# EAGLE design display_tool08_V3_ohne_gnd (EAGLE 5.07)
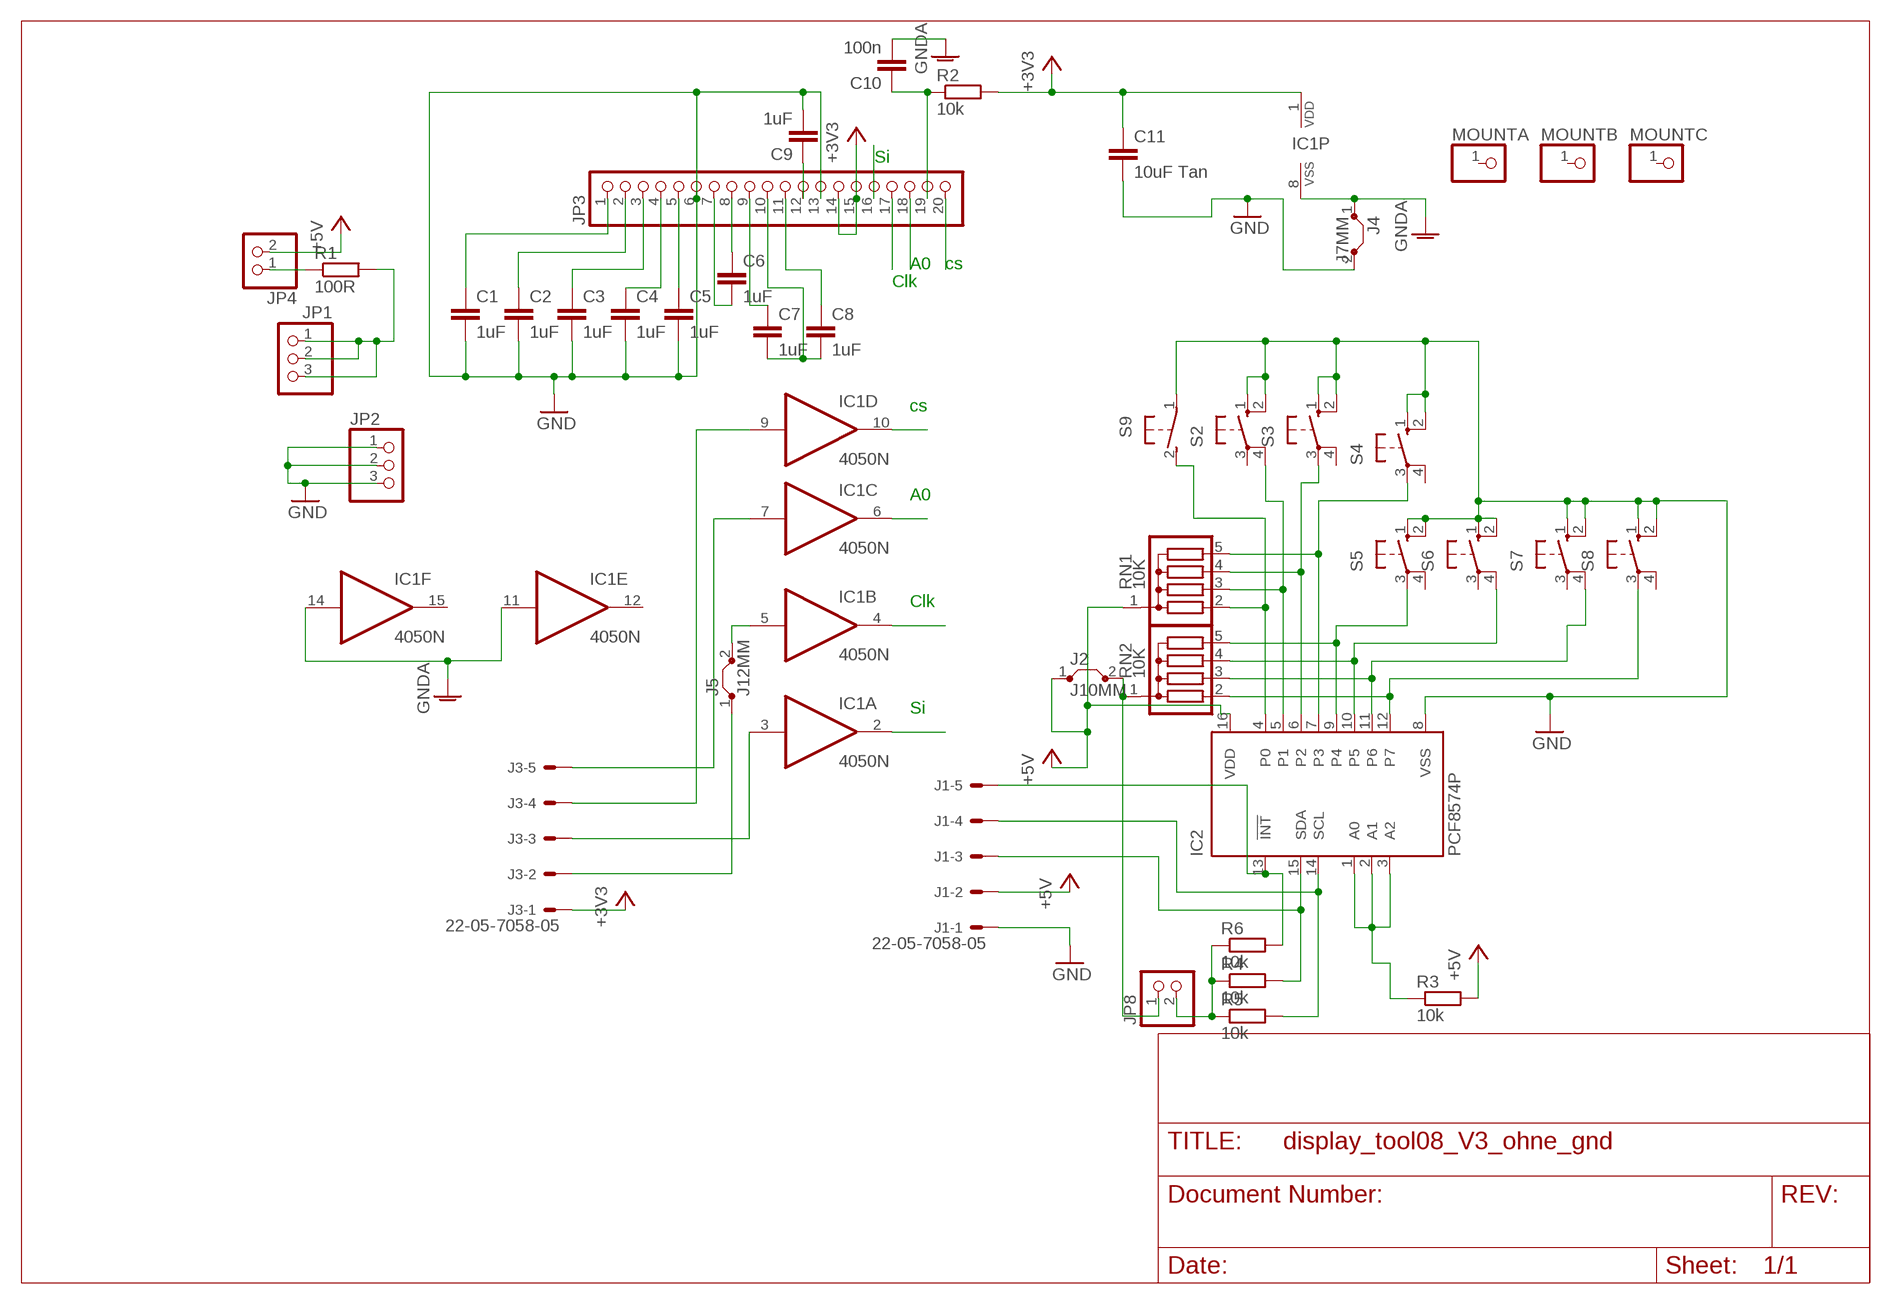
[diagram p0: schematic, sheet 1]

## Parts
C1  1uF  C-EU025-025X050  [C025-025X050]
C2  1uF  C-EU025-025X050  [C025-025X050]
C3  1uF  C-EU025-025X050  [C025-025X050]
C4  1uF  C-EU025-025X050  [C025-025X050]
C5  1uF  C-EU025-025X050  [C025-025X050]
C6  1uF  C-EU025-025X050  [C025-025X050]
C7  1uF  C-EU025-025X050  [C025-025X050]
C8  1uF  C-EU025-025X050  [C025-025X050]
C9  1uF  C-EU025-025X050  [C025-025X050]
C10  100n  C-EU025-025X050  [C025-025X050]
C11  10uF Tan  C-EU025-025X050  [C025-025X050]
IC1  4050N  [DIL16]
IC2  PCF8574P  [DIL16]
J1  22-05-7058-05  [7395-05]
J2  J10MM  [10]
J3  22-05-7058-05  [7395-05]
J4  J7MM  [07]
J5  J12MM  [12]
JP1  PINHD-1X3  [1X03]
JP2  PINHD-1X3  [1X03]
JP3  PINHD-1X20  [1X20]
JP4  PINHD-1X2  [1X02]
JP8  PINHD-1X2  [1X02]
MOUNTA  PINHD-1X1  [1X01]
MOUNTB  PINHD-1X1  [1X01]
MOUNTC  PINHD-1X1  [1X01]
R1  100R  R-EU_0309/12  [0309/12]
R2  10k  R-EU_0309/12  [0309/12]
R3  10k  R-EU_0207/7  [0207/7]
R4  10k  R-EU_0207/7  [0207/7]
R5  10k  R-EU_0207/7  [0207/7]
R6  10k  R-EU_0207/7  [0207/7]
RN1  10K  G04R  [SIL5]
RN2  10K  G04R  [SIL5]
S2  10-XX  [B3F-10XX]
S3  10-XX  [B3F-10XX]
S4  10-XX  [B3F-10XX]
S5  10-XX  [B3F-10XX]
S6  10-XX  [B3F-10XX]
S7  10-XX  [B3F-10XX]
S8  10-XX  [B3F-10XX]
S9  31-XX  [B3F-31XX]

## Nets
+3V3 [big]: C11.1 IC1.1(P:VDD) J3.1 JP3.14 JP3.15 R2.2
+5V: IC2.16(VDD) J1.2 J2.1 JP4.2 R3.2 RN1.1
A0 [big]: IC1.6(C:O) JP3.18
CLK: IC1.4(B:O) JP3.17
CS [signal]: IC1.10(D:O) JP3.20
GND: C1.2 C2.2 C3.2 C4.2 C5.2 C9.2 C11.2 IC2.8(VSS) J1.1 J4.2 JP2.1 JP2.2 JP2.3 JP3.6 JP3.13 S2.1(S) S2.2(S1) S3.1(S) S3.2(S1) S4.1(S) S4.2(S1) S5.1(S) S5.2(S1) S6.1(S) S6.2(S1) S7.1(S) S7.2(S1) S8.1(S) S8.2(S1) S9.1(P)
GNDA: C10.2 IC1.8(P:VSS) IC1.11(E:I) IC1.14(F:I) J4.1
N$1: JP4.1 R1.1
N$2: JP1.1 JP1.2 JP1.3 R1.2
N$3: IC2.7(P3) RN1.5 S4.3(P)
N$4: IC2.12(P7) RN2.2 S8.3(P)
N$5 [big]: C1.1 JP3.1
N$6 [big]: C2.1 JP3.2
N$7 [big]: C3.1 JP3.3
N$8 [big]: C4.1 JP3.4
N$9 [big]: C5.1 JP3.5
N$10: IC2.6(P2) RN1.4 S3.3(P)
N$11: IC2.11(P6) RN2.3 S7.4(P1)
N$12 [big]: C6.2 JP3.7
N$13 [big]: C6.1 JP3.8
N$14 [big]: C7.2 C8.2 JP3.10
N$15: IC2.5(P1) RN1.3 S2.4(P1)
N$16 [big]: C7.1 JP3.9
N$17 [big]: C8.1 JP3.11
N$18 [big]: C9.1 JP3.12
N$19 [big]: C10.1 JP3.19 R2.1
N$20: IC2.10(P5) RN2.4 S6.4(P1)
N$21: IC2.4(P0) RN1.2 S9.2(S)
N$22: IC2.9(P4) RN2.5 S5.3(P)
N$25 [signal]: IC1.3(A:I) J3.3
N$26 [big]: J3.2 J5.1
N$27 [signal]: IC1.7(C:I) J3.5
N$28: IC1.9(D:I) J3.4
N$29 [big]: IC1.5(B:I) J5.2
N$30: IC2.13(!INT) J1.5 R6.2
N$31: IC2.1(A0) IC2.2(A1) IC2.3(A2) R3.1
N$34: J2.2 JP8.1 RN2.1
N$35: JP8.2 R4.1 R5.1 R6.1
SCL: IC2.14(SCL) J1.4 R5.2
SDA: IC2.15(SDA) J1.3 R4.2
SI: IC1.2(A:O) JP3.16
Unconnected: IC1.12(E:O) IC1.15(F:O) MOUNTA.1 MOUNTB.1 MOUNTC.1 S2.3(P) S3.4(P1) S4.4(P1) S5.4(P1) S6.3(P) S7.3(P) S8.4(P1)

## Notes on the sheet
- Si
- A0 | cs
- Clk
- cs
- A0
- Clk
- Si

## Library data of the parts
C1-C11 = rcl:C-EU: CAPACITOR, European symbol
IC1 = 40xx:4050: Hex non-inverting BUFFER
IC2 = micro-philips:PCF8574: I2C-Bus Remote 8-bit I/O expander http://www.semiconductors.philips.com/acrobat_download/datasheets/PCF8574_4.pdf
J1 J3 = con-molex:22-?-05: CONNECTOR wire to board 2.54 mm (.1 inch) pitch header
J2 J4 J5 = jumper:J: Bridge
JP1 JP2 = pinhead:PINHD-1X3: PIN HEADER
JP3 = pinhead:PINHD-1X20: PIN HEADER
JP4 JP8 = pinhead:PINHD-1X2: PIN HEADER
MOUNTA MOUNTB MOUNTC = pinhead:PINHD-1X1: PIN HEADER
R1-R6 = rcl:R-EU_: RESISTOR, European symbol
RN1 RN2 = resistor-sil:G04R: SIL RESISTOR
S2-S8 = switch-omron:10-XX: OMRON SWITCH
S9 = switch-omron:31-XX: OMRON SWITCH

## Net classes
0 default: width 0.813 mm, drill 1.016 mm, clearance 0.762 mm
1 signal: width 0.813 mm, drill 1.016 mm, clearance 0.762 mm to class 0, clearance 0.762 mm
2 big: width 1.27 mm, clearance 0.762 mm to class 0, clearance 0.762 mm to class 1, clearance 0.762 mm

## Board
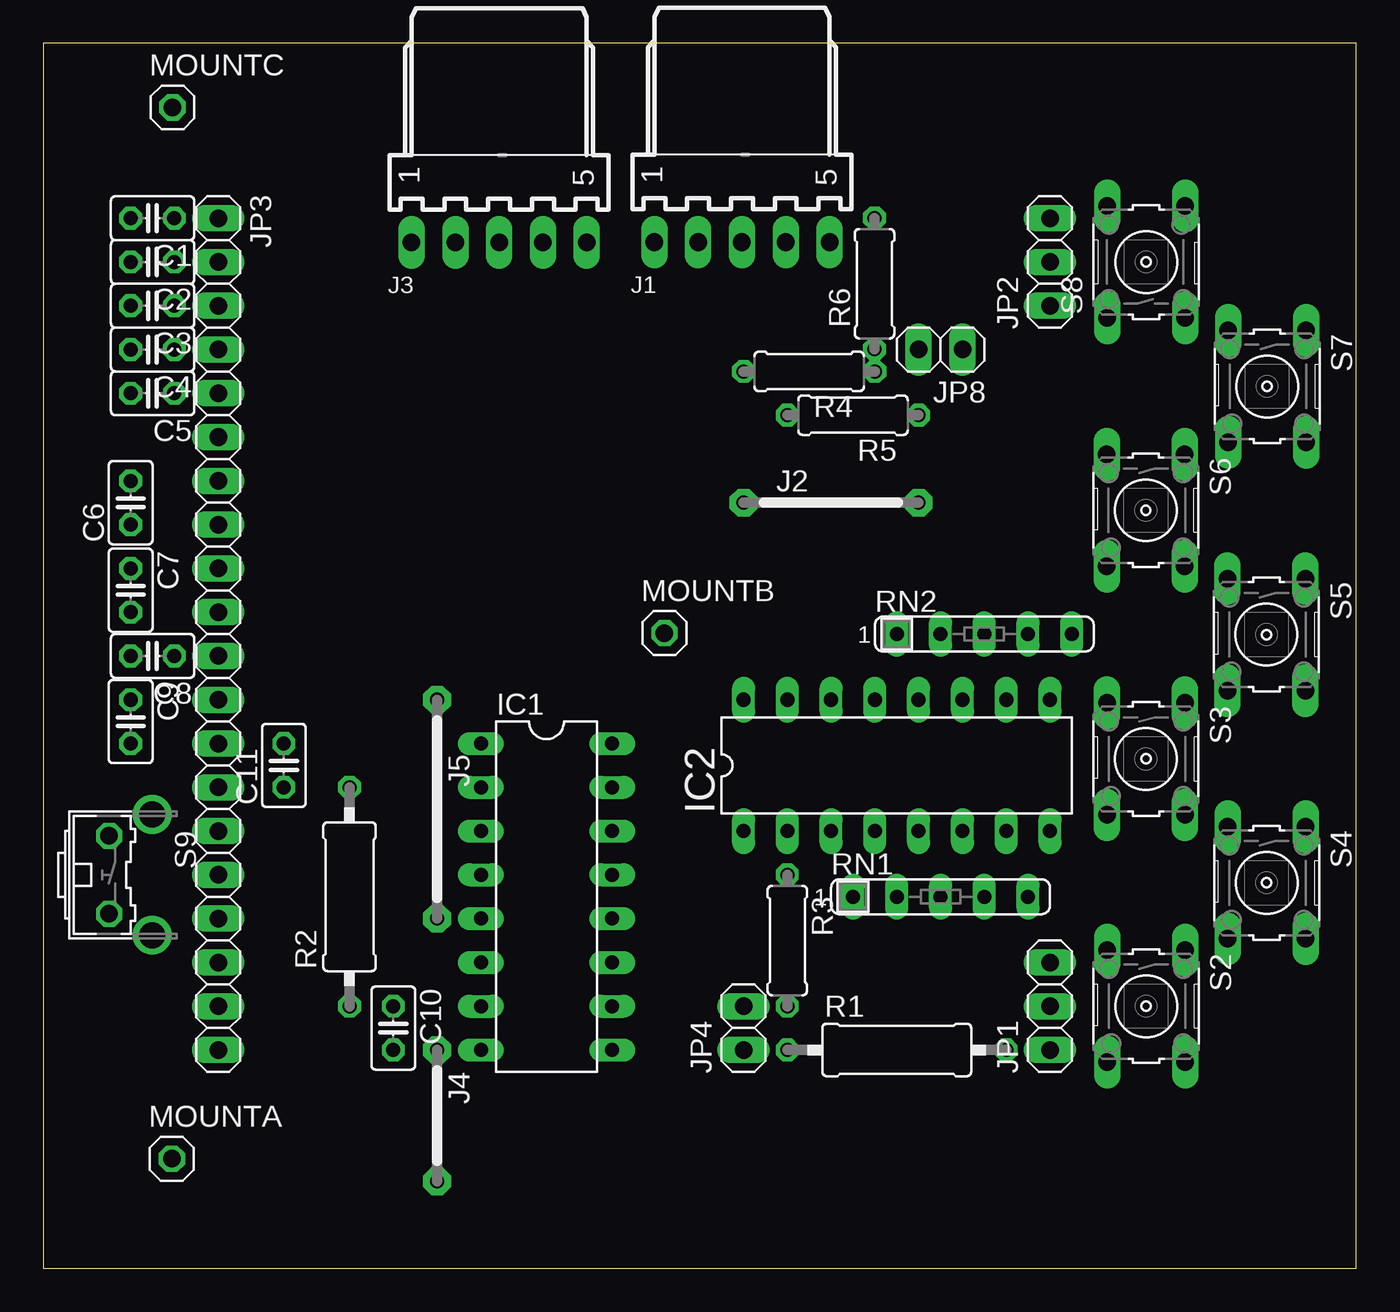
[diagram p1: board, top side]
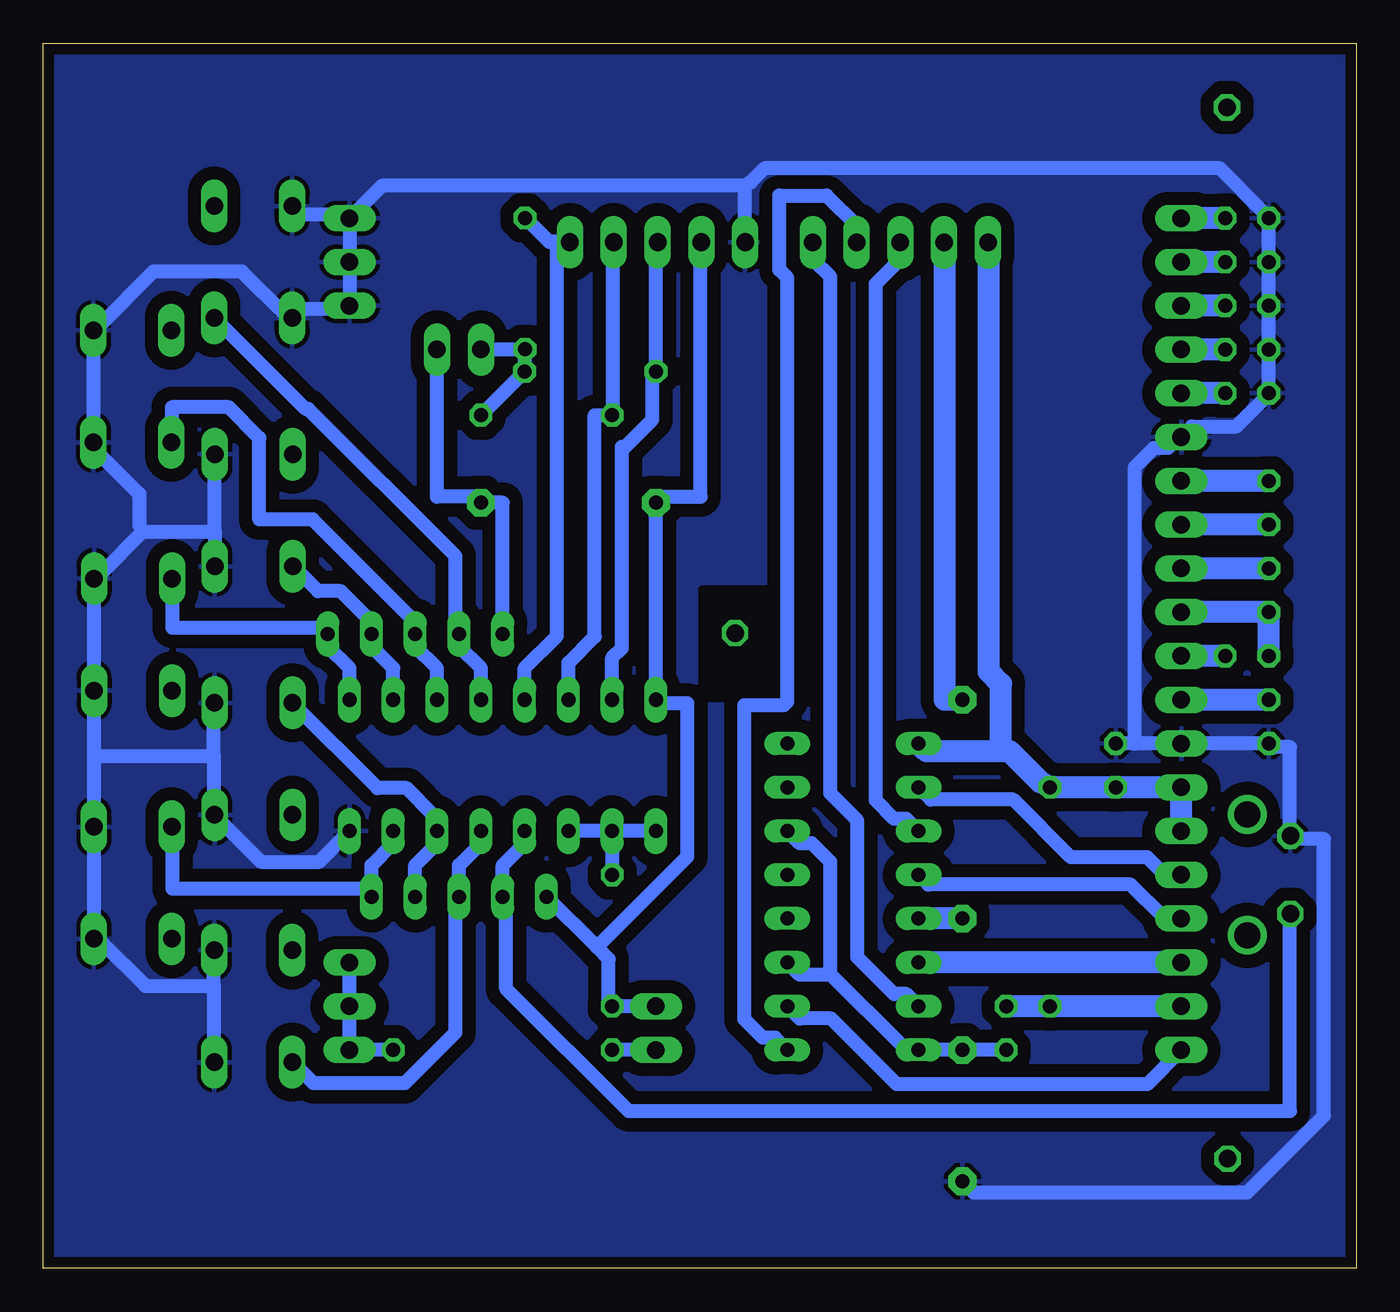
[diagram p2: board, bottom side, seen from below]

Size 76.2 x 71.12 mm. Coordinates in mm from the lower left corner, seen from the top.
Outline: 76.19,0.03 0,0.03 0,71.12 76.2,71.12 76.2,0
Copper layers (1*16): Top 0.035mm / dielectric 1.5mm / Bottom 0.035mm
Design rules "default *": minimum track width 10mil, minimum drill 24mil, track to track 8mil, track to pad 8mil, pad to pad 8mil, via to via 8mil, smd to smd 8mil, copper to edge 25mil, drill to drill 8mil, minimum pad ring 10mil, minimum via ring 8mil, stop-mask expansion 4mil, vias tented up to drill 0mil, thermal gap 10mil
bRestrict: area 33.4,33.1 to 37.9,39.4

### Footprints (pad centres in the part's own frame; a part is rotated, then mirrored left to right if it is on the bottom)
C025-025X050 = drill 0.813 octagon: 1 -1.27,0; 2 1.27,0
DIL16 = drill 0.813 long: 1 -8.89,-3.81; 2 -6.35,-3.81; 3 -3.81,-3.81; 4 -1.27,-3.81; 5 1.27,-3.81; 6 3.81,-3.81; 7 6.35,-3.81; 8 8.89,-3.81; 9 8.89,3.81; 10 6.35,3.81; 11 3.81,3.81; 12 1.27,3.81; 13 -1.27,3.81; 14 -3.81,3.81; 15 -6.35,3.81; 16 -8.89,3.81
7395-05 = drill 1.016 long: 1 5.08,0; 2 2.54,0; 3 0,0; 4 -2.54,0; 5 -5.08,0
10 = drill 0.813 pad 1.6 octagon: 1 -5.08,0; 2 5.08,0
07 = drill 0.813 pad 1.6 octagon: 1 -3.81,0; 2 3.81,0
12 = drill 0.813 pad 1.6 octagon: 1 -6.35,0; 2 6.35,0
1X03 = drill 1.016 long: 1 -2.54,0; 2 0,0; 3 2.54,0
1X20 = drill 1.016 long: 1 -24.13,0; 2 -21.59,0; 3 -19.05,0; 4 -16.51,0; 5 -13.97,0; 6 -11.43,0; 7 -8.89,0; 8 -6.35,0; 9 -3.81,0; 10 -1.27,0; 11 1.27,0; 12 3.81,0; 13 6.35,0; 14 8.89,0; 15 11.43,0; 16 13.97,0; 17 16.51,0; 18 19.05,0; 19 21.59,0; 20 24.13,0
1X02 = drill 1.016 long: 1 -1.27,0; 2 1.27,0
1X01 = drill 1.016 octagon: 1 0,0
0309/12 = drill 0.813 octagon: 1 -6.35,0; 2 6.35,0
0207/7 = drill 0.813 octagon: 1 -3.81,0; 2 3.81,0
SIL5 = drill 0.813 long: 1 -5.08,0; 2 -2.54,0; 3 0,0; 4 2.54,0; 5 5.08,0
B3F-10XX = drill 1.016 long: 1 -3.251,2.261; 2 3.251,2.261; 3 -3.251,-2.261; 4 3.251,-2.261
B3F-31XX = drill 1.016 octagon: 1 -2.261,-1.245; 2 2.261,-1.245 | drill 1.499 pad 2.159 round: 3 -3.505,1.245; 4 3.505,1.245

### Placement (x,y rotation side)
C1  6.35,60.96 180 top
C2  6.35,58.42 180 top
C3  6.35,55.88 180 top
C4  6.35,53.34 180 top
C5  6.35,50.8 180 top
C6  5.08,44.45 90 top
C7  5.08,39.37 270 top
C8  6.35,35.56 180 top
C9  5.08,31.75 270 top
C10  20.32,13.97 270 top
C11  13.97,29.21 90 top
IC1  29.21,21.59 270 top
IC2  49.53,29.21 0 top
J1  40.55,59.57 180 top
J2  45.72,44.45 0 top
J3  26.46,59.55 180 top
J4  22.86,8.89 270 top
J5  22.86,26.67 270 top
JP1  58.42,15.24 90 top
JP2  58.42,58.42 90 top
JP3  10.16,36.83 270 top
JP4  40.64,13.97 90 top
JP8  52.07,53.34 180 top
MOUNTA  7.47,6.39 0 top
MOUNTB  36.05,36.89 0 top
MOUNTC  7.51,67.39 0 top
R1  49.53,12.7 0 top
R2  17.78,21.59 90 top
R3  43.18,19.05 270 top
R4  44.45,52.07 180 top
R5  46.99,49.53 180 top
R6  48.24,57.16 90 top
RN1  52.07,21.59 0 top
RN2  54.61,36.83 0 top
S2  64,15.24 270 top
S3  63.99,29.59 270 top
S4  70.99,22.4 270 top
S5  70.98,36.8 270 top
S6  63.98,44.01 270 top
S7  71.02,51.2 270 top
S8  64,58.42 90 top
S9  5.08,22.86 270 top

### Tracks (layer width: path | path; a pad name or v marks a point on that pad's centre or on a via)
+3V3
  Bottom 1.27: IC1.1 24.94,30.02 20.62,30.02 | 20.62,30.02 20.12,30.02 18.34,28.25 R2.2 C11.1 JP3.14 JP3.15 | J3.1 21.34,59.54 21.34,34.65 20.62,33.93 20.62,30.02
+5V
  Bottom 0.813: JP4.2 R3.2 43.38,15.6 43.38,17.98 44.07,18.67 | 44.07,18.67 RN1.1 | J1.2 38.05,59.54 38.05,44.81 40.44,44.81 J2.1 IC2.16 40.28,32.82 38.81,32.82 38.81,23.93 44.07,18.67
A0
  Bottom 1.27: JP3.18 IC1.6
CLK
  Bottom 0.813: IC1.4 24.84,22.3 13.11,22.3 11.12,20.32 JP3.17
CS
  Bottom 0.813: IC1.10 32.31,14.53 30.48,14.53 26.67,10.72 12.14,10.72 JP3.20
GND
  Bottom 0.813: 12.85,30.48 C11.2 | 12.85,30.48 JP3.13 C9.2 4.72,30.28 3.86,30.28 3.86,25.15 S9.1 3.45,24.94 1.88,24.94 1.88,8.89 6.35,4.42 22.2,4.42 J4.2 | 12.85,30.48 12.85,46.53 11.73,47.65 10.92,47.65 10.52,48.06 JP3.6 9.55,48.87 6.96,48.87 5.33,50.49 C5.2 C4.2 C3.2 C2.2 C1.2 5.33,61.27 7.92,63.86 34.34,63.86 35.15,63.04 35.51,62.84 | 35.51,62.84 35.51,59.59 J1.1 | 35.51,62.84 56.54,62.84 JP2.3 | S8.2 61.72,61.67 61.21,61.16 58.78,61.16 JP2.3 | JP2.3 JP2.2 JP2.1 58.78,55.68 61.21,55.68 61.72,55.17 S8.1 62.13,55.32 64.67,57.86 69.8,57.86 72.95,54.71 S7.1 73.3,54.41 73.3,47.95 S7.2 73.2,47.55 70.61,44.96 70.61,43.13 70.41,42.77 | IC2.8 60.2,23.62 63.55,23.62 66.24,26.31 S3.2 66.29,26.72 66.29,29.77 | 66.29,29.77 66.29,32.82 S3.1 | 66.24,42.77 66.24,47.24 S6.1 | 66.24,42.77 66.24,40.79 S6.2 | 66.29,16.41 66.29,18.49 S2.1 | 66.29,16.41 66.29,11.99 S2.2 | 66.29,16.41 70.26,16.41 72.85,19 S4.2 73.25,25.6 S4.1 73.3,26.06 73.25,26.06 73.25,29.77 | 73.25,29.77 73.25,33.12 S5.2 73.25,33.58 73.25,40.03 S5.1 72.9,40.28 70.41,42.77 | 70.41,42.77 66.24,42.77 | 73.25,29.77 66.29,29.77
  pour Bottom (isolate 0.25): 0.25,0 76.15,0 76.15,71.07 0.15,71.07 0.15,-0.15
GNDA
  Bottom 0.813: C10.2 J4.1 IC1.8 25.76,12.9 26.31,12.9 30.48,17.07 30.53,17.07 | IC1.11 32.31,17.07 30.53,17.07 | IC1.14 32.31,24.69 31.6,24.69 30.53,23.62 30.53,17.07
N$1
  Bottom 0.813: JP4.1 R1.1
N$2
  Bottom 0.813: R1.2 JP1.1 JP1.2 JP1.3
N$3
  Bottom 0.813: IC2.7 55.88,24.69 57.15,23.42 RN1.5 57.51,22.05 68.68,22.05 68.68,25.6 S4.3
N$4
  Bottom 0.813: IC2.12 50.8,34.85 52.07,36.12 RN2.2 52.27,37.19 52.27,41.35 60.81,49.89 60.96,49.89 66.24,55.17 S8.3
N$5
  Bottom 1.27: C1.1 JP3.1
N$6
  Bottom 1.27: C2.1 JP3.2
N$7
  Bottom 1.27: C3.1 JP3.3
N$8
  Bottom 1.27: C4.1 JP3.4
N$9
  Bottom 1.27: C5.1 JP3.5
N$10
  Bottom 0.813: RN1.4 54.61,23.42 53.34,24.69 IC2.6 53.54,25.76 53.54,26.31 55.12,27.89 56.79,27.89 61.72,32.82 S3.3
N$11
  Bottom 0.813: IC2.11 53.34,34.85 54.61,36.12 RN2.3 54.81,37.19 54.81,37.74 60.55,43.48 63.65,43.48 63.65,48.21 65.43,49.99 68.73,49.99 68.73,47.95 S7.4
N$12
  Bottom 1.27: C6.2 JP3.7
N$13
  Bottom 1.27: C6.1 JP3.8
N$14
  Bottom 1.27: C8.2 C7.2 JP3.10
N$15
  Bottom 0.813: IC2.5 50.8,24.69 52.07,23.42 RN1.3 52.27,21.23 52.27,13.72 55.22,10.77 60.5,10.77 61.72,11.99 S2.4
N$16
  Bottom 1.27: C7.1 JP3.9
N$17
  Bottom 1.27: C8.1 JP3.11
N$18
  Bottom 1.27: C9.1 JP3.12
N$19
  Bottom 1.27: C10.1 R2.1 JP3.19
N$20
  Bottom 0.813: IC2.10 55.88,34.85 57.15,36.12 RN2.4 57.35,37.19 57.35,37.74 58.93,39.32 60.25,39.32 61.67,40.74 S6.4
N$21
  Bottom 0.813: IC2.4 48.26,24.69 49.53,23.42 RN1.2 49.33,21.23 49.33,16.26 42.22,9.14 3.86,9.14 3.86,20.57 S9.2
N$22
  Bottom 0.813: IC2.9 58.42,34.85 59.69,36.12 RN2.5 59.89,37.19 68.68,37.19 68.68,40.03 S5.3
N$25
  Bottom 0.813: IC1.3 26.11,26.11 26.82,26.11 27.89,27.18 27.89,57.15 26.47,58.57 26.47,59.54 J3.3
N$26
  Bottom 1.27: J5.1 23.88,33.02 23.88,59.54 J3.2
N$27
  Bottom 0.813: IC1.7 26.11,15.95 26.82,15.95 28.96,18.09 28.96,26.01 30.53,27.58 30.53,57.56 31.5,58.52 31.5,59.54 J3.5
N$28
  Bottom 0.813: IC1.9 33.73,13.41 34.44,13.41 35.51,14.48 35.51,32.72 33.22,32.72 33.02,32.92 33.02,57.51 33.48,57.96 33.48,62.28 30.73,62.28 29.01,60.55 29.01,59.59 J3.4
N$29
  Bottom 1.27: J5.2 IC1.5
N$30
  Bottom 0.813: R6.2 48.21,60.96 46.84,59.59 45.67,59.59 J1.5 46.38,59.23 46.38,36.73 48.26,34.85 IC2.13
N$31
  Bottom 0.813: IC2.1 IC2.2 | IC2.2 R3.1 | IC2.2 IC2.3
N$34
  Bottom 0.813: RN2.1 49.53,44.45 J2.2 51,44.81 53.34,44.81 JP8.1
N$35
  Bottom 0.813: R5.1 48.56,51.77 48.51,51.77 R4.1 48.26,53.34 R6.1 48.67,53.34 JP8.2
SCL
  Bottom 0.813: IC2.14 45.72,35.15 44.2,36.68 44.2,49.53 R5.2 43.13,49.89 43.13,59.54 J1.4
SDA
  Bottom 0.813: J1.3 40.59,59.54 40.64,59.54 R4.2 40.84,51.71 40.84,49.28 42.42,47.7 42.62,47.7 42.62,36.02 43.18,35.46 IC2.15
SI
  Bottom 0.813: IC1.2 24.69,27.23 19.91,27.23 16.56,23.88 12.14,23.88 11.12,22.86 JP3.16

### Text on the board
bText: WWW.SAMMELLOTHAR.DE | EMC2 PENDANT GLCD | WWW.LINUXCNC.ORG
